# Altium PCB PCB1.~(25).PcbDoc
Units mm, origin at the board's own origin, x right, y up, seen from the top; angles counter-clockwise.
Board outline 152.4 x 101.6 mm, 2 copper layers (Top Layer, Bottom Layer); 16 components, 17 nets, 64 pads, 4 vias.
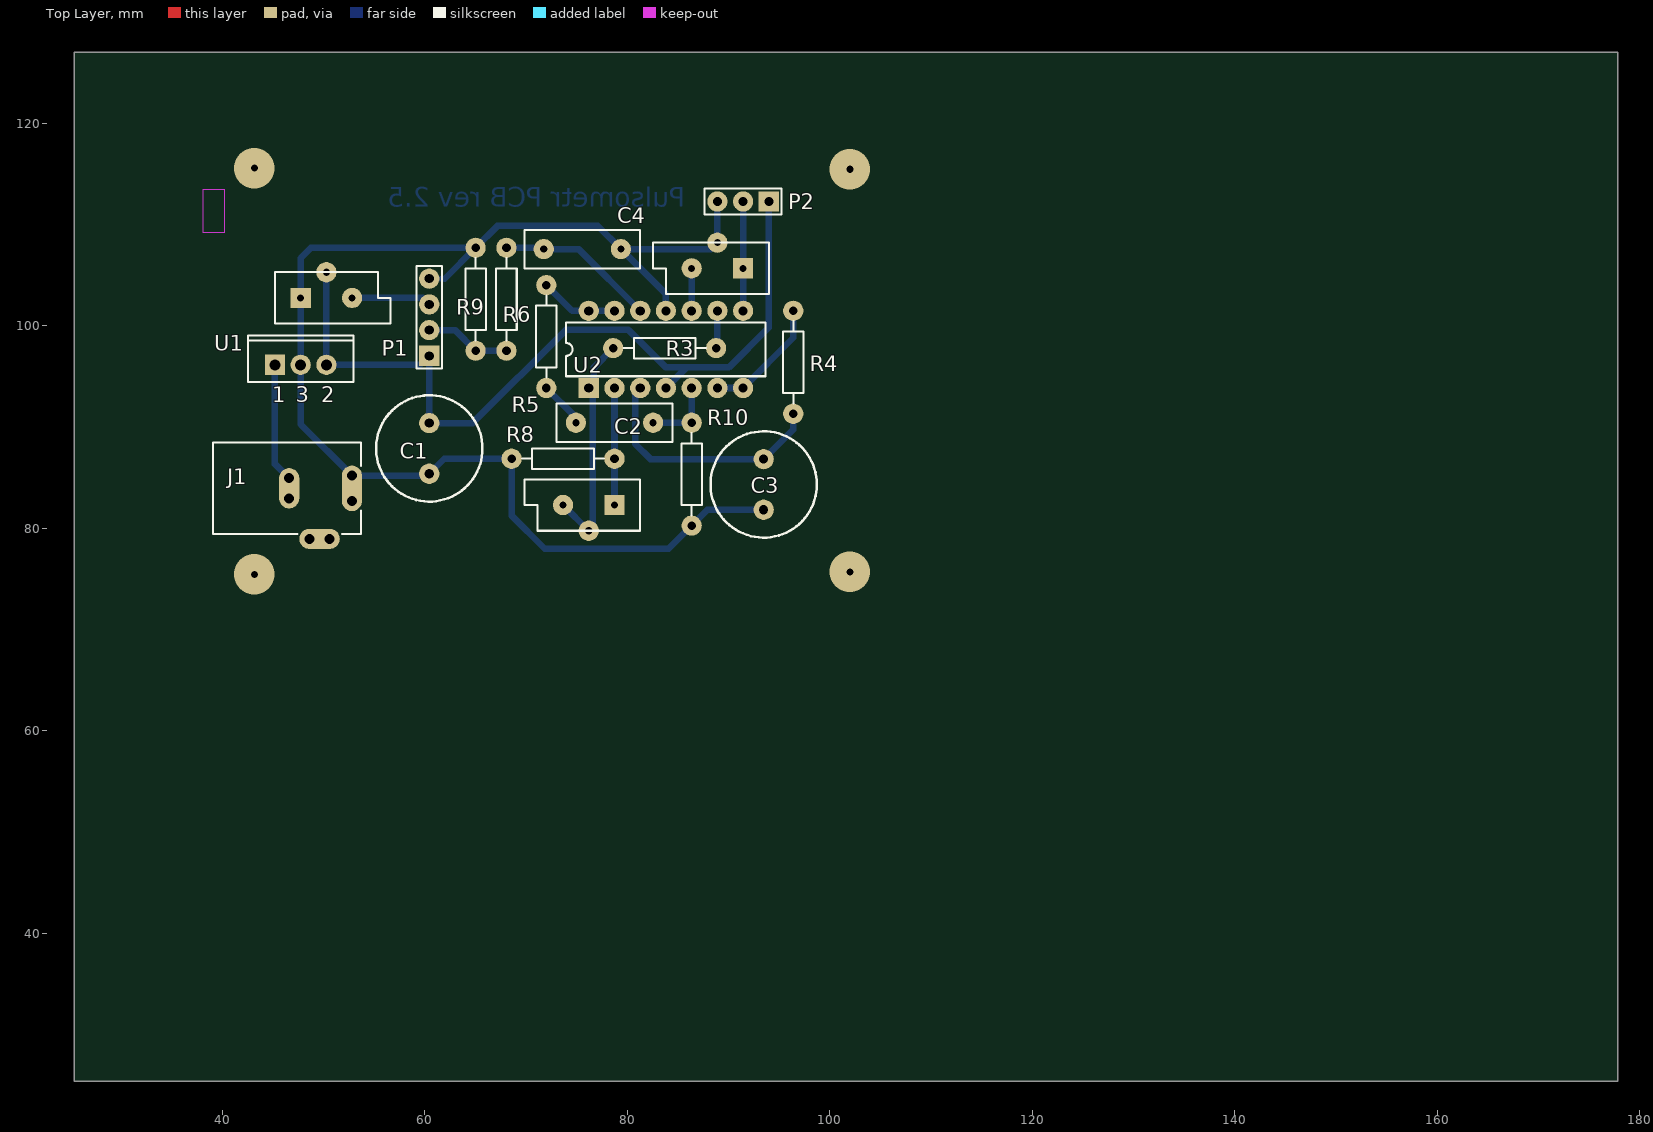
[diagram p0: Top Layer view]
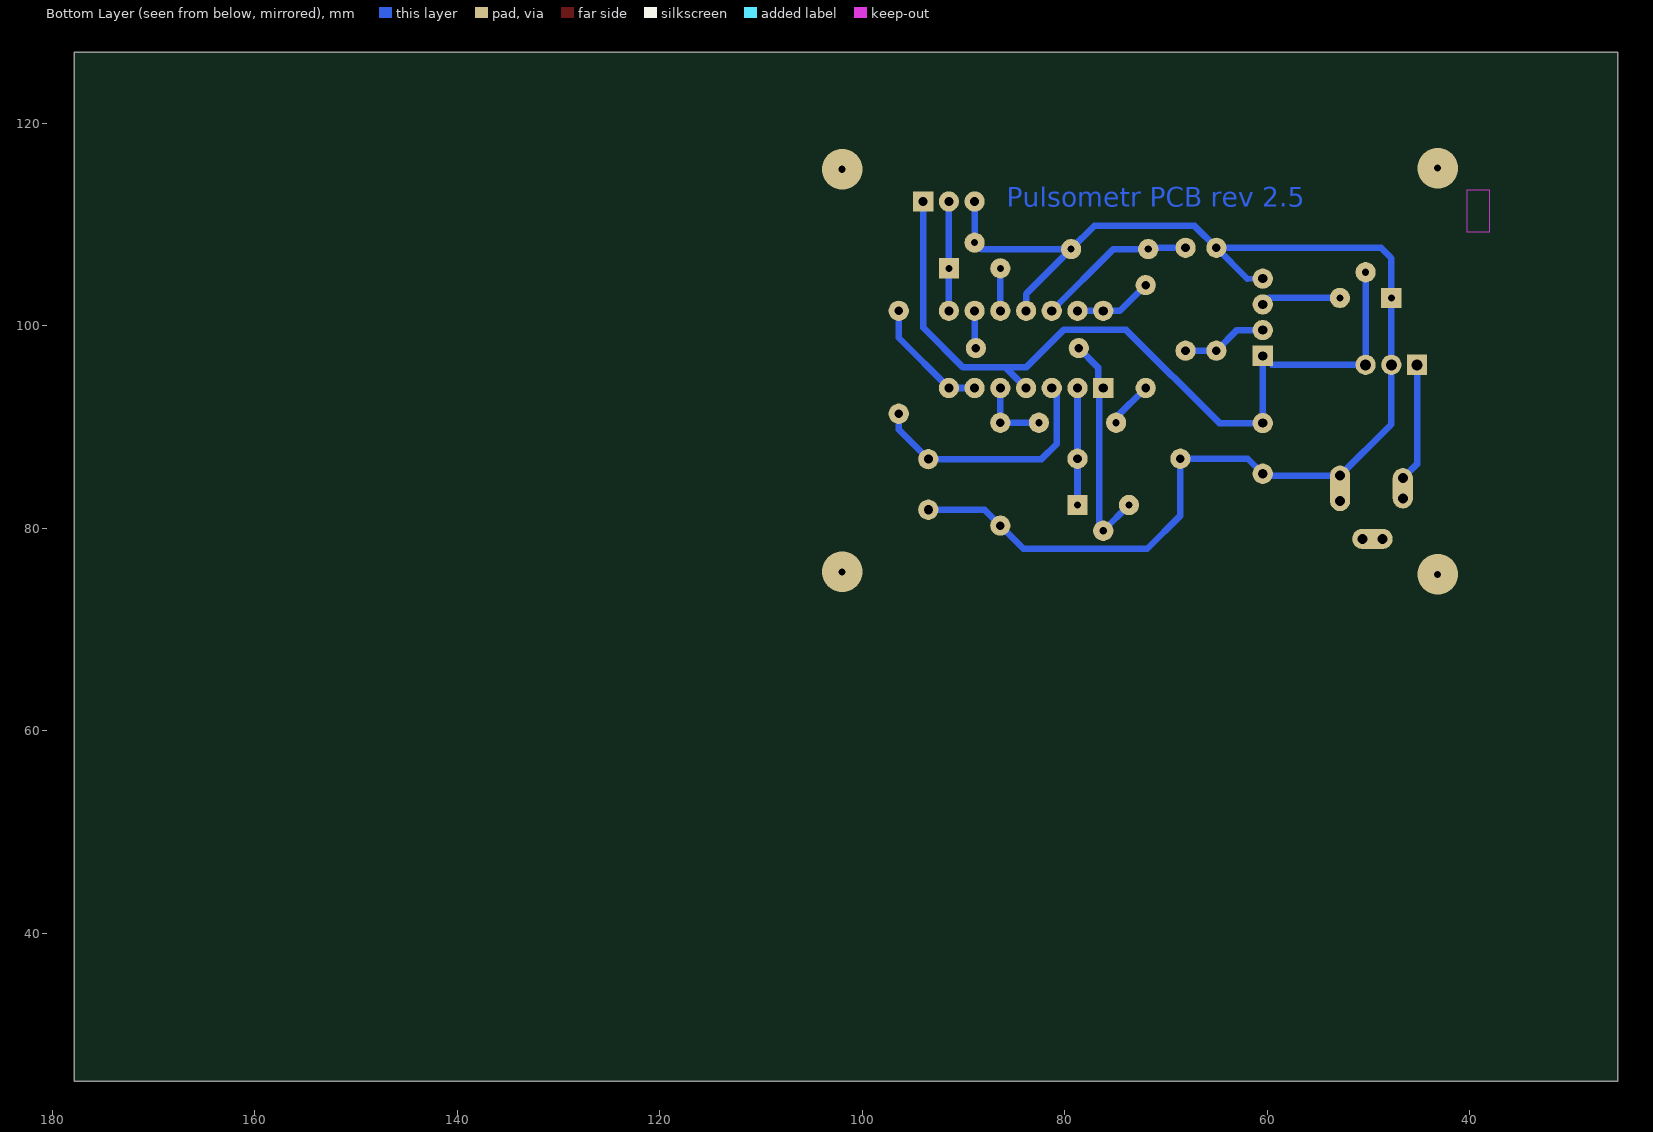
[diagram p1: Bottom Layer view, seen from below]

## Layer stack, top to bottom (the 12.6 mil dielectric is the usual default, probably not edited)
Top Layer: signal copper 0.0356
Dielectric: dielectric 0.32, FR-4, Dk 4.8
Bottom Layer: signal copper 0.0356

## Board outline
25.4,25.4 177.8,25.4 177.8,127 25.4,127

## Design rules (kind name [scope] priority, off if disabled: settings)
Clearance [All] p1: gap=0.254
ComponentClearance [All] p1: gap=0.254 collisioncheckmode=3 verticalgap=0.254
HoleSize [All] p1: absolutevalues=TRUE maxlimit=2.54 minlimit=0.05 maxpercent=80.000 minpercent=20.000
PolygonConnect [All] p1: connectstyle=Relief reliefconductorwidth=0.254 reliefentries=4 polygonreliefangle="90 Angle"
RoomDefinition Sheet1 [InComponentClass('Sheet1')] p1: confinementstyle=ConfineIn formatcopy=TRUE lockcomponents=FALSE outline 36.576,75.565 101.981,75.565 101.981,115.443 36.576,115.443
RoutingTopology [All] p1: topology=Daisy_Simple
RoutingVias [All] p1: holewidth=0.711 width=2 viastyle="Through Hole" minholewidth=0.711 minwidth=1.27 maxholewidth=0.711 maxwidth=2.27
SolderMaskExpansion [All] p1: expansion=0.102
TestPointUsage [All] p1: valid=0 allowmultiple=FALSE
Testpoint [All] p1: side=7 testpointundercomponent=TRUE minsize=1.016 maxsize=2.54 preferedsize=1.524 minholesize=0 maxholesize=1.016 preferedholesize=0.813 testpointgrid=0.025 style=1021 order=0-112345678
Width [All] p1: maxlimit=1254 minlimit=0.254 preferedwidth=0.254 toplayer_minwidth=0.65 toplayer_maxwidth=1.254 toplayer_prefwidth=0.65 bottomlayer_minwidth=0.65 bottomlayer_prefwidth=0.65 minimp=50.000000 maximp=50.000000 favimp=50.000000
16 further rules are at their usual default settings.

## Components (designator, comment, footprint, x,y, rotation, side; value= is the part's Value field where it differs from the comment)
C1 "Cap Pol1" RB5-10.5 60.452,87.884 r90 top
C2 "Cap" RAD-0.3 78.74,90.424 r180 top
C3 "Cap Pol1" RB5-10.5 93.472,84.328 r270 top
C4 "Cap" RAD-0.3 75.565,107.569 r180 top
J1 "PWR2.5" KLD-0202 39.116,83.947 r0 top
P1 "Header 4" HDR1X4 60.452,97.028 r90 top
P2 "Header 3" HDR1X3 93.98,112.268 r180 top
R3 "Res2" AXIAL-0.4 83.693,97.79 r180 top
R4 "Res2" AXIAL-0.4 96.393,96.393 r90 top
R5 "Res2" AXIAL-0.4 72.009,98.933 r90 top
R6 "Res2" AXIAL-0.4 68.072,102.616 r270 top
R8 "Res2" AXIAL-0.4 73.66,86.868 r180 top
R9 "Res2" AXIAL-0.4 65.024,102.616 r270 top
R10 "Res2" AXIAL-0.4 86.36,85.344 r270 top
U1 "L7812ABV" TO220ABN 47.752,96.139 r0 top
U2 "LM324AN" N14A 83.82,97.663 r0 top

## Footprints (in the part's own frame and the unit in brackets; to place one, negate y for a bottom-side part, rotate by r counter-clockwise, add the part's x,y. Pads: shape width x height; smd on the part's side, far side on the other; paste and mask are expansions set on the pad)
AXIAL-0.4 [mm] "Resistor; 2 Leads"
  round 2 hole 0.85: 1(-5.08,0) 2(5.08,0)
  silkscreen extent -4.06,-1.02 4.06,1.02
HDR1X3 [mm] "Connector; Header; 3 Position"
  rect 2x2 hole 0.9: 1(0,0)
  round 2 hole 0.9: 2(2.54,0) 3(5.08,0)
  silkscreen extent -1.27,-1.27 6.35,1.27
HDR1X4 [mm] "Connector; Header; 4 Position"
  rect 2x2 hole 0.9: 1(0,0)
  round 2 hole 0.9: 2(2.54,0) 3(5.08,0) 4(7.62,0)
  silkscreen extent -1.27,-1.27 8.89,1.27
KLD-0202 [mm] "DC Power Jack, 2.5mm, KLD Series, PCB Mount"
  oval 2x4.5 all layers, no hole: 1(13.7,0)
  round 1.5 hole 1: 1A(13.7,-1.25) 1B(13.7,1.25) 2B(7.5,1) 3A(9.5,-5) 3B(11.5,-5)
  oval 2x4 all layers, no hole: 2(7.5,0)
  round 2 hole 1: 2A(7.5,-1)
  oval 4x2 all layers, no hole: 3(10.5,-5)
  silkscreen extent 0,-4.5 14.6,4.5
N14A [mm] "DIP; 14 Leads; Row Spacing 7.62 mm; Pitch 2.54 mm"
  rect 2x2 hole 0.9: 1(-7.62,-3.81)
  round 2 hole 0.9: 2(-5.08,-3.81) 3(-2.54,-3.81) 4(0,-3.81) 5(2.54,-3.81) 6(5.08,-3.81) 7(7.62,-3.81) 8(7.62,3.81) 9(5.08,3.81) 10(2.54,3.81) 11(0,3.81) 12(-2.54,3.81) 13(-5.08,3.81) 14(-7.62,3.81)
  silkscreen extent -9.85,-2.65 9.85,2.65
RAD-0.3 [mm] "Capacitor; 2 Leads"
  round 2 hole 0.7: 1(-3.81,0) 2(3.81,0)
  silkscreen extent -5.71,-1.91 5.71,1.91
RB5-10.5 [mm] "Motor, General Kind; 2 Leads"
  round 2 hole 0.9: 1(-2.5,0) 2(2.5,0)
  silkscreen extent -5.25,-5.25 5.25,5.25
TO220ABN [mm] "TO, Thru-Hole, Vertical, Heatsink Mounted; 3 In-Line Leads; Pitch 2.54 mm; Pin sequence 1, 3, 2"
  rect 2x2 hole 1.1: 1(-2.54,0)
  round 2 hole 1.1: 2(2.54,0) 3(0,0)
  silkscreen extent -5.2,-1.7 5.2,2.9

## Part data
C1 C3: "Polarized Capacitor (Radial)"
C2 C4: "Capacitor"
J1: "Low Voltage Power Supply Connector"
P1: "Header, 4-Pin"
P2: library part "Header 2", "Header, 2-Pin"
R3 R4 R5 R6 R8 R9 R10: "Resistor"
U1: "Precision 1A Regulator"
U2: "Low-Power Quad Operational Amplifier"

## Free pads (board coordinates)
  rect 2x2 hole 0.7: 1(47.752,102.743) 1(78.74,82.296) 1(91.44,105.664)
  round 2 hole 0.7 unplated: 2(50.292,105.283)
  round 2 hole 0.7: 2(76.2,79.756) 2(88.9,108.204) 3(52.832,102.743) 3(73.66,82.296) 3(86.36,105.664)

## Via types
v1: diameter 4, hole 0.711, Top Layer to Bottom Layer, 4 vias

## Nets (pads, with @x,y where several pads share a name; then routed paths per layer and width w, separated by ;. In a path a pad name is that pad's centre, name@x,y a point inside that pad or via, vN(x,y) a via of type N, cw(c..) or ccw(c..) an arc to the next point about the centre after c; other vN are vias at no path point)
+5: C1.2 P1.1 P2.1 pad.2@50.292,105.283 U1.2 U2.4 | length 82.1
  Bottom Layer w0.54: P1.1@59.563,96.139 P1.1
  Bottom Layer w0.65: pad.2@50.292,105.283 U1.2 P1.1@59.563,96.139 ; P1.1 C1.2 64.73,90.384 73.939,99.593 80.112,99.593 83.82,95.885 85.852,95.885 ; U2.4 85.852,95.885 ; P2.1 93.98,99.822 90.043,95.885 85.852,95.885
GND: C1.1 C3.2 C4.1 J1.1 J1.1A J1.1B P1.4 P2.3 pad.1@47.752,102.743 pad.2@88.9,108.204 R8.2 R9.1 R10.2 U1.3 U2.11 | length 139
  Bottom Layer w0.54: J1.1A J1.1 ; C1.1@60.265,85.197 C1.1 ; P1.4 61.976,104.648 ; pad.2@88.265,107.569 pad.2@88.9,108.204
  Bottom Layer w0.65: J1.1A 52.558,82.955 52.558,83.947 52.558,84.939 J1.1B ; C1.1@60.265,85.197 J1.1B ; C1.1 61.936,86.868 R8.2 68.58,81.255 71.857,77.978 84.074,77.978 R10.2 87.924,81.828 C3.2 ; 61.976,104.648 R9.1 ; U2.11 83.82,103.124 C4.1 ; pad.2@88.265,107.569 C4.1 ; pad.2@88.9,108.204 P2.3 ; J1.1B 47.752,90.261 U1.3 47.752,102.743 47.752,106.68 48.768,107.696 R9.1 ; R9.1 67.183,109.855 77.089,109.855 C4.1
NetC2_1: C2.1 R10.1 U2.5 | length 7.2
  Bottom Layer w0.65: C2.1 R10.1 U2.5
NetC2_2: C2.2 R5.1 | length 4.6
  Bottom Layer w0.54: C2.2 C2.2@74.93,90.932
  Bottom Layer w0.65: R5.1 C2.2@74.93,90.932
NetC3_1: C3.1 R4.1 U2.3 | length 24.7
  Bottom Layer w0.65: U2.3 80.772,93.345 80.772,88.352 82.296,86.828 C3.1 96.393,89.749 R4.1
NetC4_2: C4.2 R6.1 U2.12 | length 15.8
  Bottom Layer w0.65: R6.1 71.628,107.696 C4.2 75.184,107.569 U2.12
NetJ1_3: J1.3 J1.3A J1.3B | length 2
  Bottom Layer w0.54: J1.3A J1.3 J1.3B
NetP1_2: P1.2 R6.2 R9.2 | length 8.5
  Bottom Layer w0.65: P1.2 62.992,99.568 R9.2 R6.2
NetP1_3: P1.3 pad.3@52.832,102.743 | length 7.9
  Bottom Layer w0.54: P1.3@59.817,102.743 P1.3
  Bottom Layer w0.65: pad.3@52.832,102.743 P1.3@59.817,102.743
NetP2_2: P2.2 pad.1@91.44,105.664 U2.8 | length 10.8
  Bottom Layer w0.65: U2.8 91.44,105.664 P2.2
NetR2_1: pad.1@78.74,82.296 R8.1 U2.2 | length 11.6
  Bottom Layer w0.65: pad.1@78.74,82.296 R8.1 U2.2
NetR2_2: pad.2@76.2,79.756 pad.3@73.66,82.296 R3.2 U2.1 | length 22.7
  Bottom Layer w0.65: pad.3@73.66,82.296 76.2,79.756 76.581,80.137 76.581,93.345 76.2,93.726 U2.1 ; U2.1@76.644,93.839 76.708,95.885 R3.2
NetR3_1: R3.1 U2.9 | length 3.7
  Bottom Layer w0.65: R3.1 88.9,97.917 U2.9
NetR4_2: R4.2 U2.6 U2.7 | length 12.2
  Bottom Layer w0.65: U2.6 U2.7 96.393,98.806 R4.2
NetR5_2: R5.2 U2.13 U2.14 | length 7.8
  Bottom Layer w0.65: R5.2 74.549,101.473 U2.14 U2.13
NetR7_3: pad.3@86.36,105.664 U2.10 | length 4.2
  Bottom Layer w0.65: U2.10 pad.3@86.36,105.664
VCC: J1.2 J1.2A J1.2B U1.1 | length 15.2
  Bottom Layer w0.54: J1.2A J1.2 J1.2B
  Bottom Layer w0.65: U1.1 45.212,86.351 J1.2B 47.116,84.447 J1.2
copper on no net:
  other v1: 43.18,75.438 101.981,75.692 101.981,115.443 43.18,115.57

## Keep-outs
Keep-Out Layer:
  rectangle: 38.1,109.22 40.259,113.411

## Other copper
Bottom Layer:
  text "Pulsometr PCB rev 2.5" at 85.725,111.76 h1.9

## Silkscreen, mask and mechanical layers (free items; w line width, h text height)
Top Overlay:
  lines w0.2: 45.212,100.203 45.212,105.283 55.372,105.283 55.372,102.743 56.642,102.743 56.642,100.203 45.212,100.203 ; 69.85,82.296 69.85,84.836 81.28,84.836 81.28,79.756 71.12,79.756 71.12,82.296 69.85,82.296 ; 82.55,105.664 82.55,108.204 93.98,108.204 93.98,103.124 83.82,103.124 83.82,105.664 82.55,105.664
